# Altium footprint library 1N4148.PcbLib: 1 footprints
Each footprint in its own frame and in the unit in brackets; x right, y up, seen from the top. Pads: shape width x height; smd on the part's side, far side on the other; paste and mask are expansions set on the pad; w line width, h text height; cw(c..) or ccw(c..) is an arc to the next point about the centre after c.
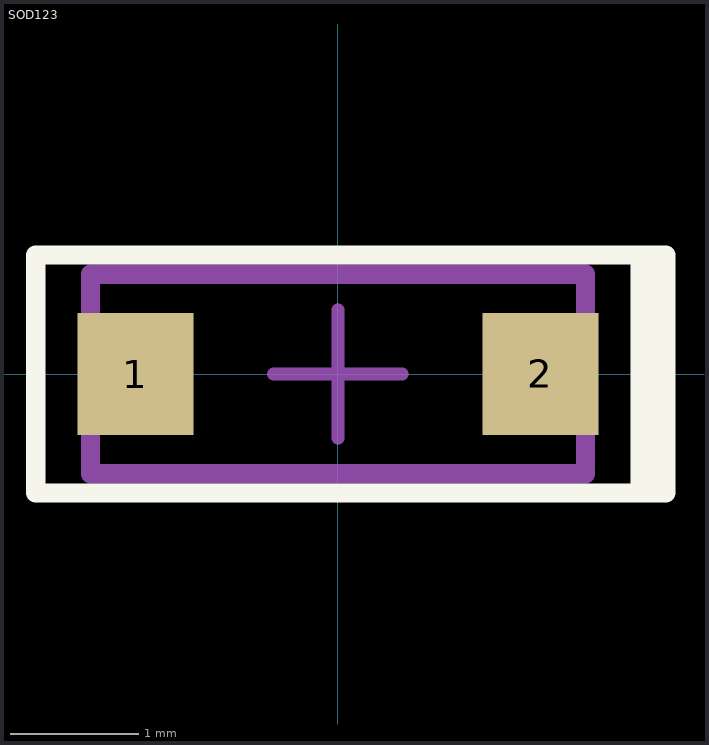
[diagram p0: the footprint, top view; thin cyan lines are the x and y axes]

## SOD123 [mm]
pads (2):
  rect 0.9x0.95 smd: 1(-1.575,0) 2(1.575,0)
Top Overlay:
  rectangle: 2.275,-0.95 2.6,0.95
  lines w0.15: -2.35,-0.925 2.55,-0.925 2.55,0.925 -2.35,0.925 -2.35,-0.925
Mechanical 13:
  lines w0.15: -1.925,-0.775 -1.925,0.775 1.925,0.775 1.925,-0.775 -1.925,-0.775
Mechanical 15:
  lines w0.1: -0.5,0 0.5,0 ; 0,-0.5 0,0.5
3D body "SOD123.step": height 1.28, standoff 0, extent -1.85,-0.8 1.85,0.8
